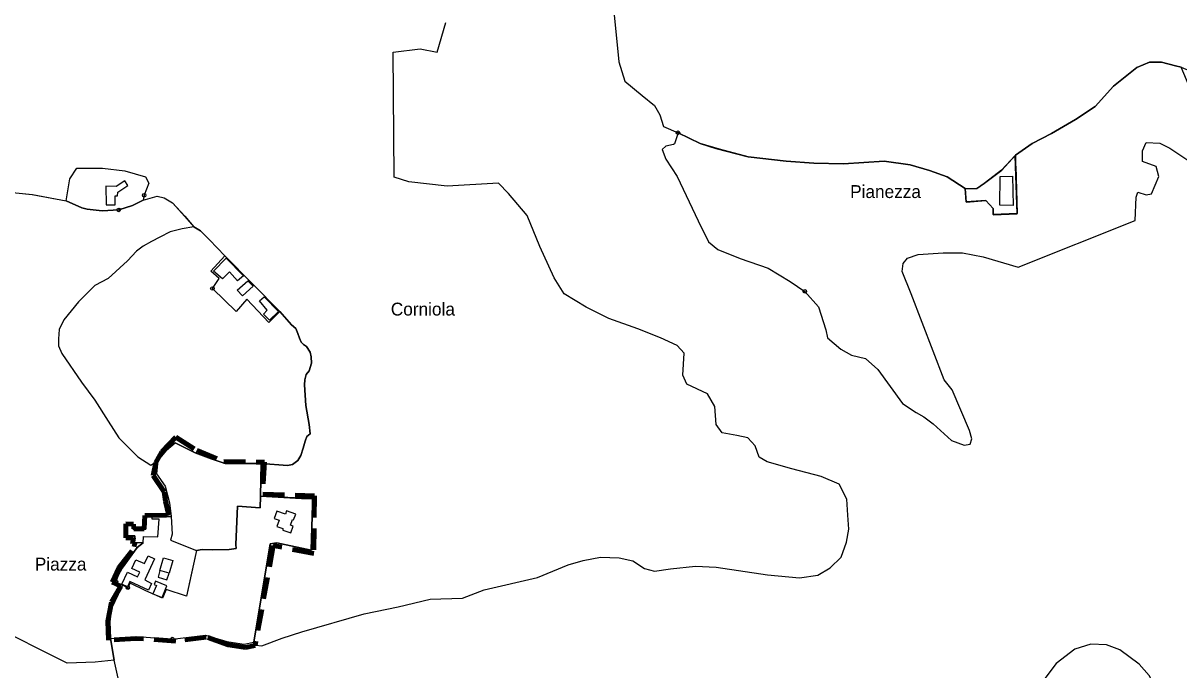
# Model space of a CAD drawing. Extents: x 652791 to 656927, y 889884 to 892405.
# Drawn here: x 655576 to 656474, y 890630 to 891133 of the extents above; entities that cross this region are included whole.
import ezdxf
from ezdxf.enums import TextEntityAlignment as Align

# ---------------------------------------------------------------- set-up
doc = ezdxf.new("R2010")
doc.units = 0
doc.header["$LTSCALE"] = 5.6
doc.header["$PDMODE"] = 32
doc.header["$PDSIZE"] = 2.8
doc.linetypes.add('MEDIUM_DASHED', pattern=[4.5, 3, -1.5])
for name, color, linetype, lineweight in [('1', 7, 'Continuous', 25), ('12', 7, 'Continuous', 25), ('2', 7, 'Continuous', 25), ('3', 7, 'Continuous', 25), ('35', 7, 'Continuous', 25), ('36', 7, 'Continuous', 25), ('37', 7, 'Continuous', 25), ('4', 7, 'Continuous', 25), ('6', 7, 'Continuous', 25), ('7', 7, 'MEDIUM_DASHED', 100)]:
    doc.layers.add(name, color=color, linetype=linetype, lineweight=lineweight)
doc.layers.add('60', color=7, linetype='Continuous')

msp = doc.modelspace()

# ---------------------------------------------------------------- linework, layer by layer
at = {"layer": '1'}
msp.add_line((655647.79, 890698.77), (655649.57, 890703.78), dxfattribs=at)
for points in [[(655649.57, 890703.78), (655652.57, 890709.54), (655664.32, 890725.65), (655668.89, 890729.13), (655662.28, 890729.46), (655662.45, 890734.52), (655656.71, 890734.52), (655656.76, 890743.16), (655660.15, 890743.1), (655661.16, 890739.83), (655670.97, 890739.81), (655671.21, 890749.71), (655690.79, 890749.71), (655691.6, 890735.82), (655690.08, 890731.27), (655710.46, 890723.26)], [(655710.46, 890723.26), (655702.73, 890687.68), (655702.73, 890687.68), (655686.92, 890692.88), (655683.99, 890686.3)], [(655683.99, 890686.3), (655671.13, 890691.84), (655658.88, 890697.92), (655657.03, 890694.32)]]:
    msp.add_lwpolyline(points, dxfattribs=at)
for points in [[(655656.76, 890743.16), (655656.71, 890734.52), (655662.45, 890734.52), (655662.28, 890729.46), (655665.58, 890729.3), (655668.89, 890729.13), (655669.21, 890734), (655680.33, 890733.88), (655681.28, 890747.57), (655675.84, 890747.65), (655675.92, 890749.55), (655671.21, 890749.71), (655670.97, 890739.81), (655661.16, 890739.83), (655660.15, 890743.1)], [(655663.36, 890716.08), (655669.96, 890713), (655672.8, 890719.08), (655677.85, 890716.72), (655670.25, 890700.46), (655675.47, 890697.47), (655673.05, 890692.3), (655658.63, 890699.05), (655656.71, 890694.98), (655652.27, 890697.08), (655656.67, 890706.41), (655664.53, 890702.7), (655666.26, 890706.37), (655660.14, 890709.26)], [(655684.82, 890717.43), (655691.99, 890715.33), (655689.19, 890705.47), (655682.02, 890707.57)], [(655682.02, 890707.57), (655680.64, 890702.48), (655687.34, 890700.47), (655689.19, 890705.47)], [(655678.56, 890699.41), (655677.5, 890696.82), (655679.23, 890696.11), (655676.52, 890689.53), (655683.62, 890686.61), (655687.38, 890695.77)]]:
    msp.add_lwpolyline(points, close=True, dxfattribs=at)
for p in [(655647.79, 890698.77), (655657.03, 890694.32)]:
    msp.add_point(p, dxfattribs=at)
at = {"layer": '12'}
for points in [[(655760.74, 890790.66), (655732.63, 890790.72), (655721.67, 890794.44), (655709.28, 890799.08), (655707.66, 890799.98), (655706.87, 890800.29), (655693.81, 890806.84), (655687.08, 890801.22), (655680.47, 890792.99), (655679.34, 890782.76), (655686.08, 890773.27), (655689.34, 890760.2), (655690.79, 890749.71), (655691.6, 890735.82)], [(655710.46, 890723.26), (655714.74, 890724.03), (655722.92, 890723.72), (655735.74, 890723.97), (655741.29, 890724.86), (655740.98, 890727.97), (655742.36, 890757.53), (655759.74, 890756.34), (655760.24, 890765.34), (655760.74, 890790.66)], [(655754.95, 890652.05), (655767.67, 890728.28), (655772.86, 890729.16), (655799.61, 890723.34), (655800.55, 890758.9), (655800.55, 890763.53), (655791.98, 890763.72), (655760.24, 890765.34), (655759.74, 890756.34), (655742.36, 890757.53)], [(655742.36, 890757.53), (655740.98, 890727.97), (655741.29, 890724.86)], [(655691.6, 890735.82), (655690.08, 890731.27), (655710.46, 890723.26)], [(655710.46, 890723.26), (655706.6, 890705.47), (655702.73, 890687.68), (655686.92, 890692.88), (655683.99, 890686.3), (655671.13, 890691.84), (655658.88, 890697.92), (655657.03, 890694.31), (655653.01, 890696.25), (655649.42, 890689.08), (655644.24, 890678.15), (655643.15, 890667.92), (655643.55, 890654.98), (655663.88, 890656.42), (655671.37, 890655.88), (655691.59, 890654.42)], [(655741.29, 890724.86), (655735.74, 890723.97), (655722.92, 890723.72), (655714.74, 890724.03), (655710.46, 890723.26)], [(655691.59, 890654.42), (655717.46, 890657.36), (655733.95, 890652.58), (655747.37, 890650.41), (655754.95, 890652.05)]]:
    msp.add_lwpolyline(points, dxfattribs=at)
at = {"layer": '2'}
for points in [[(655609.01, 890994.88), (655611.84, 891011.93), (655617.48, 891020.1), (655637.34, 891020.1), (655654.68, 891018.08), (655670.8, 891013.54), (655673.43, 891008.6), (655669.7, 890999.12), (655668.99, 890995.18), (655660.62, 890991.15), (655649.94, 890987.72)], [(655649.94, 890987.72), (655637.19, 890986.97), (655625.49, 890988.27), (655621.19, 890989.37), (655609.01, 890994.88)]]:
    msp.add_lwpolyline(points, dxfattribs=at)
msp.add_lwpolyline([(655639.96, 891006.08), (655640.06, 890991.55), (655647.12, 890991.55), (655647.12, 890998.61), (655649.11, 890998.71), (655649.24, 891001.64), (655657.1, 891006.68), (655654.78, 891010.31), (655647.92, 891005.97)], close=True, dxfattribs=at)
msp.add_point((655649.94, 890987.72), dxfattribs=at)
at = {"layer": '3'}
for points in [[(655721.56, 890940.03), (655732.42, 890952.03), (655775.12, 890908.95), (655766.69, 890900.17), (655749.39, 890918.47), (655741.09, 890908.87), (655722.79, 890926.67)], [(655722.79, 890926.67), (655728.05, 890934.38), (655721.56, 890940.03)]]:
    msp.add_lwpolyline(points, dxfattribs=at)
for points in [[(655730.48, 890934.33), (655723.67, 890940.16), (655733.34, 890950.13), (655746.86, 890936.65), (655742.33, 890932.56), (655735.97, 890939.6)], [(655742.05, 890925.4), (655750.34, 890932.64), (655754.3, 890928.4), (655746.01, 890921.06)], [(655759.32, 890917.09), (655762.9, 890920.32), (655774.01, 890908.76), (655767.09, 890902.2), (655762.33, 890906.83), (655765.29, 890909.98)]]:
    msp.add_lwpolyline(points, close=True, dxfattribs=at)
msp.add_point((655722.79, 890926.67), dxfattribs=at)
at = {"layer": '35'}
msp.add_line((655647.79, 890698.77), (655653.01, 890696.26), dxfattribs=at)
for points in [[(655557.14, 891002.34), (655582.82, 890999.62), (655609.01, 890994.88), (655621.19, 890989.37), (655625.49, 890988.27), (655637.19, 890986.97), (655649.94, 890987.72), (655660.62, 890991.15), (655668.99, 890995.18), (655679.88, 890998.36), (655685.32, 890997.23), (655691.81, 890993.28), (655701.38, 890982.75)], [(655701.38, 890982.75), (655708.23, 890974.6), (655699.33, 890972.91)], [(655699.33, 890972.91), (655690, 890970.58), (655682, 890966.58), (655675.34, 890963.24), (655669.01, 890959.58), (655663.68, 890955.58), (655656.69, 890948.25), (655641.7, 890934.58), (655631.37, 890928.91), (655618.71, 890916.25), (655607.39, 890902.25), (655603.72, 890894.92), (655603.06, 890887.59), (655603.06, 890882.25), (655605.72, 890876.25), (655621.04, 890853.92), (655631.37, 890839.92), (655641.7, 890823.59), (655650.02, 890810.59), (655664.68, 890795.93), (655675.01, 890789.59), (655680.47, 890792.99), (655679.34, 890782.76), (655686.08, 890773.27), (655689.34, 890760.2), (655690.79, 890749.71)], [(655690.79, 890749.71), (655671.21, 890749.71), (655670.97, 890739.81), (655661.16, 890739.83), (655660.15, 890743.1), (655656.76, 890743.16), (655656.71, 890734.52), (655662.45, 890734.52), (655662.28, 890729.46), (655668.89, 890729.13), (655664.32, 890725.65), (655652.57, 890709.54), (655649.57, 890703.78), (655647.79, 890698.77)], [(655653.01, 890696.25), (655649.42, 890689.08), (655644.24, 890678.15), (655643.15, 890667.92), (655643.55, 890654.98), (655646.5, 890637.96), (655641.53, 890637.43)], [(655641.53, 890637.43), (655631.75, 890636.44), (655609.85, 890635.63), (655548.75, 890666.18)]]:
    msp.add_lwpolyline(points, dxfattribs=at)
msp.add_lwpolyline([(655693.81, 890806.84), (655709.28, 890799.08), (655721.67, 890794.44), (655732.63, 890790.72), (655760.74, 890790.66), (655781.06, 890789.26), (655785.07, 890790.12), (655789.08, 890792.99), (655791.38, 890797.01), (655793.39, 890802.75), (655794.82, 890808.2), (655796.25, 890811.64), (655798.83, 890813.93), (655797.97, 890821.11), (655795.39, 890835.74), (655794.82, 890843.77), (655794.25, 890851.81), (655794.53, 890855.82), (655795.68, 890859.84), (655797.97, 890862.71), (655799.69, 890868.73), (655799.41, 890873.61), (655798.83, 890877.34), (655795.97, 890881.64), (655793.67, 890883.08), (655791.66, 890885.09), (655790.52, 890888.24), (655789.08, 890891.68), (655787.65, 890895.7), (655784.21, 890898.57), (655775.12, 890908.95), (655766.69, 890900.17), (655749.39, 890918.47), (655741.09, 890908.87), (655722.79, 890926.67), (655728.05, 890934.38), (655721.56, 890940.03), (655732.42, 890952.03), (655720.55, 890964.56), (655713.39, 890971.44), (655708.23, 890974.6), (655699.33, 890972.91), (655690, 890970.58), (655682, 890966.58), (655675.34, 890963.24), (655669.01, 890959.58), (655663.68, 890955.58), (655656.69, 890948.25), (655641.7, 890934.58), (655631.37, 890928.91), (655618.71, 890916.25), (655607.39, 890902.25), (655603.72, 890894.92), (655603.06, 890887.59), (655603.06, 890882.25), (655605.72, 890876.25), (655621.04, 890853.92), (655631.37, 890839.92), (655641.7, 890823.59), (655650.02, 890810.59), (655664.68, 890795.93), (655675.01, 890789.59), (655680.47, 890792.99), (655687.08, 890801.22)], close=True, dxfattribs=at)
at = {"layer": '36'}
for points in [[(656034.63, 891141.71), (656038.53, 891102.67), (656043.15, 891087.83), (656056.63, 891076.54), (656066.21, 891068.79)], [(656107.51, 890844.89), (656091.53, 890852.4), (656088.44, 890859.4), (656089.47, 890876.4), (656083.8, 890882.4), (656070.91, 890888.4), (656053.38, 890895.4), (656030.7, 890903.41), (656013.18, 890912.12), (655996, 890922.49), (655988.42, 890934.91), (655984.3, 890943.92), (655977.08, 890959.42), (655967.29, 890983.42), (655952.85, 891000.43), (655945.15, 891008.51), (655905.11, 891006.15), (655875.32, 891009.61), (655863.98, 891013.11), (655863.11, 891110.32), (655884.21, 891112.73), (655897.47, 891110.32), (655904.1, 891133.25)], [(656066.21, 891068.79), (656070.39, 891061.56), (656073.22, 891052.53), (656084.58, 891047.69), (656081.74, 891038.98), (656081.03, 891038.65), (656075, 891037.36), (656072.16, 891034.78), (656075, 891027.04), (656083.87, 891013.81), (656100.19, 890979.29), (656108.35, 890962.84), (656115.44, 890957.03), (656132.76, 890949.96), (656154.75, 890942.54), (656171.78, 890932.22), (656183.14, 890924.48), (656193.78, 890912.54), (656199.46, 890894.48), (656200.88, 890888.35), (656211.17, 890879.63), (656219.33, 890874.8), (656230.32, 890872.21), (656239.9, 890863.83), (656259.06, 890837.37), (656269.71, 890830.27), (656275.74, 890827.05), (656282.83, 890821.56), (656297.03, 890808.66), (656306.96, 890805.11), (656311.57, 890805.76), (656312.99, 890809.95), (656311.22, 890816.4), (656297.73, 890848.02), (656291.35, 890855.76), (656265.83, 890922.44), (656258.73, 890939.86), (656259.44, 890945.99), (656262.99, 890950.18), (656271.15, 890953.09)], [(656271.15, 890953.09), (656290.75, 890954.4), (656305.7, 890954.4), (656321.68, 890951.4), (656348.97, 890943.33), (656439.8, 890979.46), (656440.51, 890997.53), (656441.93, 891001.4), (656448.32, 890999.46), (656452.57, 891000.11), (656458.25, 891013.66), (656456.12, 891021.4), (656445.48, 891025.27), (656445.48, 891033.66), (656448.32, 891040.11), (656458.96, 891039.47), (656466.77, 891035.6), (656481.67, 891025.92)], [(655761.27, 890649.28), (655776.89, 890655.05), (655792.34, 890660.05), (655840.64, 890674.02), (655867.17, 890679.45), (655892.03, 890685.35), (655917.21, 890686.09), (655934.03, 890692.7), (655975.29, 890702.29), (655999.14, 890712.01), (656010.98, 890715.31), (656024.41, 890717.97), (656038.96, 890717.41), (656049.45, 890715.17), (656058.55, 890709.29), (656066.25, 890707.05), (656078.7, 890709.01), (656098.15, 890710.97), (656114.24, 890710.13), (656154.01, 890704.34), (656178.9, 890702.01), (656193.15, 890704.08), (656202.75, 890709.79), (656211.3, 890718.09), (656215.45, 890729.77), (656217.27, 890739.88), (656216.49, 890750.52), (656215.76, 890763.07), (656209.75, 890774.65), (656195.75, 890780.62), (656172.97, 890786.57), (656153.9, 890792.07), (656147.71, 890795.57), (656144.62, 890804.57), (656138.95, 890810.58), (656130.18, 890812.58), (656118.84, 890814.58), (656114.2, 890821.08), (656113.17, 890835.08), (656107.51, 890844.89)], [(655697.99, 890568.01), (655688.91, 890571.17), (655676.81, 890576.59), (655668.2, 890582.46), (655661.45, 890589.46), (655656.56, 890598.49), (655653.31, 890606.61), (655650.07, 890621.67), (655646.5, 890637.96), (655643.55, 890654.98), (655663.88, 890656.42), (655671.37, 890655.88), (655691.59, 890654.42)], [(655691.59, 890654.42), (655717.46, 890657.36), (655733.95, 890652.58), (655747.37, 890650.41), (655754.95, 890652.05), (655756.3, 890649.77), (655761.27, 890649.28)], [(656481.61, 890596.03), (656464.08, 890608.04), (656456.35, 890615.04), (656450.68, 890626.04), (656442.94, 890635.04), (656427.99, 890646.04), (656417.68, 890650.04), (656405.31, 890650.54), (656392.94, 890646.54), (656378.5, 890635.54), (656364.13, 890616.47), (656344.54, 890582.96), (656334.72, 890566.93), (656325.76, 890573.55), (656304.66, 890584.23), (656286.87, 890588.74), (656275.35, 890589.99), (656265.33, 890588.49), (656257.31, 890583.22), (656249.3, 890572.95), (656242.24, 890567.05), (656228.32, 890589.55)]]:
    msp.add_lwpolyline(points, dxfattribs=at)
msp.add_point((655691.59, 890654.42), dxfattribs=at)
at = {"layer": '37'}
msp.add_line((655669.7, 890999.12), (655668.99, 890995.18), dxfattribs=at)
for points in [[(656034.63, 891141.71), (656038.53, 891102.67), (656043.15, 891087.83), (656056.63, 891076.54), (656066.21, 891068.79)], [(656346.76, 891030.15), (656359.82, 891039.27), (656374.91, 891047.18), (656393.59, 891057.96), (656408.69, 891068.03), (656423.06, 891083.85), (656441.02, 891098.23), (656451.08, 891102.54), (656460.42, 891102.54), (656471.2, 891099.67), (656475.55, 891098.58), (656489.19, 891092.99), (656505.69, 891087.49), (656521.15, 891086.99), (656530.43, 891088.49), (656539.2, 891093.99), (656550.54, 891114), (656575.8, 891148.01)], [(656107.51, 890844.89), (656091.53, 890852.4), (656088.44, 890859.4), (656089.47, 890876.4), (656083.8, 890882.4), (656070.91, 890888.4), (656053.38, 890895.4), (656030.7, 890903.41), (656013.18, 890912.12), (655996, 890922.49), (655988.42, 890934.91), (655984.3, 890943.92), (655977.08, 890959.42), (655967.29, 890983.42), (655952.85, 891000.43), (655945.15, 891008.51), (655905.11, 891006.15), (655875.32, 891009.61), (655863.98, 891013.11), (655863.11, 891110.32), (655884.21, 891112.73), (655897.47, 891110.32), (655904.1, 891133.25)], [(656471.2, 891099.67), (656460.42, 891102.54), (656451.08, 891102.54), (656441.02, 891098.23), (656423.06, 891083.85), (656408.69, 891068.03), (656393.59, 891057.96), (656374.91, 891047.18), (656359.82, 891039.27), (656346.76, 891030.15), (656346.97, 891021.75), (656347.02, 891021.8), (656348.15, 890984.82), (656329.53, 890984.13), (656329.53, 890988.93), (656323.82, 890995.11), (656308.49, 890993.97), (656307.81, 891004.27)], [(656466.77, 891035.6), (656481.67, 891025.92), (656490.18, 891031.73), (656501.54, 891030.43), (656512.18, 891022.69), (656516.44, 891027.21), (656512.18, 891033.02), (656508.63, 891042.69), (656505.79, 891051.73), (656508.63, 891060.12), (656509.34, 891067.21), (656502.95, 891073.02), (656488.76, 891077.54), (656483.09, 891080.76), (656475.55, 891098.58), (656471.2, 891099.67)], [(656066.21, 891068.79), (656070.39, 891061.56), (656073.22, 891052.53), (656084.58, 891047.69)], [(656116.93, 891034.95), (656101.84, 891039.27), (656084.58, 891047.69), (656081.74, 891038.98), (656081.03, 891038.65), (656075, 891037.36), (656072.16, 891034.78), (656075, 891027.04), (656083.87, 891013.81), (656100.19, 890979.29), (656108.35, 890962.84), (656115.44, 890957.03), (656132.76, 890949.96), (656154.75, 890942.54), (656171.78, 890932.22), (656183.14, 890924.48)], [(656084.58, 891047.69), (656101.84, 891039.27), (656113.9, 891035.54), (656139.05, 891029.07)], [(656190.08, 891024.04), (656168.67, 891025.61), (656139.05, 891029.07), (656116.93, 891034.95)], [(656183.14, 890924.48), (656193.78, 890912.54), (656199.46, 890894.48), (656200.88, 890888.35), (656211.17, 890879.63), (656219.33, 890874.8), (656230.32, 890872.21), (656239.9, 890863.83), (656259.06, 890837.37), (656269.71, 890830.27), (656275.74, 890827.05), (656282.83, 890821.56), (656297.03, 890808.66), (656306.96, 890805.11), (656311.57, 890805.76), (656312.99, 890809.95), (656311.22, 890816.4), (656297.73, 890848.02), (656291.35, 890855.76), (656265.83, 890922.44), (656258.73, 890939.86), (656259.44, 890945.99), (656262.99, 890950.18), (656271.15, 890953.09), (656290.75, 890954.4), (656305.7, 890954.4), (656321.68, 890951.4), (656348.97, 890943.33), (656439.8, 890979.46), (656440.51, 890997.53), (656441.93, 891001.4), (656448.32, 890999.46), (656452.57, 891000.11), (656458.25, 891013.66), (656456.12, 891021.4), (656445.48, 891025.27), (656445.48, 891033.66), (656448.32, 891040.11), (656458.96, 891039.47), (656466.77, 891035.6)], [(656139.05, 891029.07), (656168.67, 891025.61), (656190.08, 891024.04), (656213.23, 891023.45), (656244.69, 891025.48), (656264.97, 891022.73), (656280.06, 891018.42), (656293.71, 891013.38), (656307.81, 891004.27), (656316.73, 891004.27), (656322.67, 891008.39), (656336.16, 891018.69), (656346.76, 891030.15)], [(656307.81, 891004.27), (656293.71, 891013.38), (656280.06, 891018.42), (656264.97, 891022.73), (656244.69, 891025.48), (656213.23, 891023.45), (656190.08, 891024.04)], [(655488.11, 891022.12), (655502.57, 891014.96), (655516.74, 891009.33), (655529.83, 891005.76), (655543.36, 891002.72), (655557.14, 891002.33), (655582.81, 890999.61), (655609.01, 890994.87), (655611.84, 891011.93), (655617.48, 891020.1), (655637.34, 891020.1), (655654.68, 891018.08), (655670.8, 891013.54), (655673.43, 891008.6), (655669.7, 890999.12)], [(655668.99, 890995.18), (655679.87, 890998.35), (655685.31, 890997.22), (655691.81, 890993.28), (655701.38, 890982.74), (655708.22, 890974.59)], [(655708.22, 890974.59), (655713.38, 890971.44), (655720.55, 890964.55), (655732.42, 890952.03), (655775.12, 890908.95)], [(655775.12, 890908.95), (655784.21, 890898.57), (655787.65, 890895.7), (655789.08, 890891.68), (655790.51, 890888.24), (655791.66, 890885.08), (655793.67, 890883.07), (655795.96, 890881.64), (655798.83, 890877.33), (655799.4, 890873.61), (655799.69, 890868.73), (655797.97, 890862.7), (655795.68, 890859.83), (655794.53, 890855.82), (655794.24, 890851.8), (655794.82, 890843.77), (655795.39, 890835.73), (655797.97, 890821.1), (655798.83, 890813.93), (655796.25, 890811.64), (655794.82, 890808.19), (655793.38, 890802.74), (655791.38, 890797), (655789.08, 890792.99), (655785.07, 890790.12), (655781.05, 890789.26), (655760.74, 890790.65), (655760.24, 890765.33), (655791.98, 890763.71)], [(655761.27, 890649.28), (655776.89, 890655.05), (655792.34, 890660.05), (655840.64, 890674.02), (655867.17, 890679.45), (655892.03, 890685.35), (655917.21, 890686.09), (655934.03, 890692.7), (655975.29, 890702.29), (655999.14, 890712.01), (656010.98, 890715.31), (656024.41, 890717.97), (656038.96, 890717.41), (656049.45, 890715.17), (656058.55, 890709.29), (656066.25, 890707.05), (656078.7, 890709.01), (656098.15, 890710.97), (656114.24, 890710.13), (656154.01, 890704.34), (656178.9, 890702.01), (656193.15, 890704.08), (656202.75, 890709.79), (656211.3, 890718.09), (656215.45, 890729.77), (656217.27, 890739.88), (656216.49, 890750.52), (656215.76, 890763.07), (656209.75, 890774.65), (656195.75, 890780.62), (656172.97, 890786.57), (656153.9, 890792.07), (656147.71, 890795.57), (656144.62, 890804.57), (656138.95, 890810.58), (656130.18, 890812.58), (656118.84, 890814.58), (656114.2, 890821.08), (656113.17, 890835.08), (656107.51, 890844.89)], [(655791.98, 890763.71), (655800.55, 890763.52), (655800.55, 890758.89), (655799.61, 890723.33), (655772.86, 890729.15), (655767.67, 890728.27), (655754.95, 890652.05), (655756.3, 890649.77), (655761.27, 890649.28)], [(655646.5, 890637.96), (655631.75, 890636.44), (655609.85, 890635.63), (655548.75, 890666.18), (655543.59, 890653.67), (655537.99, 890649.56), (655523.59, 890650.1), (655513.34, 890653.12), (655505.81, 890658.55), (655502.49, 890665.79), (655499.48, 890673.64), (655497.39, 890676.63), (655486, 890689.35), (655478.76, 890700.82), (655486, 890709.87), (655491.42, 890720.13), (655489.01, 890728.58), (655481.78, 890732.2), (655474.54, 890724.96), (655466.7, 890727.97), (655451.06, 890726.93), (655441.49, 890728.27), (655456.86, 890701.91)], [(656481.61, 890596.03), (656464.08, 890608.04), (656456.35, 890615.04), (656450.68, 890626.04), (656442.94, 890635.04), (656427.99, 890646.04), (656417.68, 890650.04), (656405.31, 890650.54), (656392.94, 890646.54), (656378.5, 890635.54), (656364.13, 890616.47), (656344.54, 890582.96), (656334.72, 890566.93)], [(655650.07, 890621.67), (655646.5, 890637.96)]]:
    msp.add_lwpolyline(points, dxfattribs=at)
for p in [(656084.58, 891047.69), (655669.7, 890999.12), (656183.14, 890924.48)]:
    msp.add_point(p, dxfattribs=at)
at = {"layer": '4'}
for points in [[(656346.91, 891021.65), (656346.7, 891030.05), (656336.1, 891018.59), (656322.61, 891008.29), (656316.67, 891004.17), (656307.75, 891004.17), (656308.43, 890993.87), (656323.76, 890995.01), (656329.47, 890988.83), (656329.47, 890984.03)], [(656329.47, 890984.03), (656348.09, 890984.72), (656346.96, 891021.7)]]:
    msp.add_lwpolyline(points, dxfattribs=at)
msp.add_lwpolyline([(656335.02, 891013.64), (656344.44, 891013.88), (656344.92, 890991.18), (656334.78, 890991.42)], close=True, dxfattribs=at)
at = {"layer": '6'}
msp.add_lwpolyline([(655787.46, 890751.41), (655780.3, 890753.95), (655779.43, 890751.5), (655772.83, 890753.85), (655770.76, 890748.01), (655774.52, 890746.67), (655772.85, 890741.96), (655777.37, 890740.35), (655777.54, 890739.02), (655783.57, 890736.87), (655785.44, 890742.15), (655783.37, 890742.89), (655784.91, 890747.22), (655785.85, 890746.89)], close=True, dxfattribs=at)
at = {"layer": '7'}
for points in [[(655651.54, 890695.38), (655644.95, 890698.68), (655649.95, 890709.67), (655663.93, 890727.59), (655660.72, 890728.36), (655661.55, 890733.16), (655655.39, 890733.04), (655655.51, 890743.84), (655661.31, 890743.65), (655661.72, 890740.12), (655669.6, 890740.12), (655670.32, 890750.3), (655688.81, 890750.73), (655686.17, 890761.43), (655685.31, 890768.68), (655676.66, 890781.33), (655678.82, 890791.44), (655683.51, 890799.79), (655694.33, 890811.11), (655710.55, 890801.05), (655731.58, 890792.37), (655763.15, 890791.72), (655761.86, 890766.91), (655802.12, 890765.61), (655801.47, 890720.82)], [(655801.47, 890720.82), (655769.99, 890727.08), (655756.03, 890649.47)], [(655756.03, 890649.47), (655748.45, 890647.83), (655735.03, 890650), (655717.9, 890655.95), (655694.37, 890652.88), (655663.29, 890654.94), (655641.94, 890653.51), (655641.36, 890668.28), (655644.23, 890683.19), (655651.54, 890695.38)]]:
    msp.add_lwpolyline(points, dxfattribs=at)

# ---------------------------------------------------------------- texts
at = {"layer": '60'}
for s, p in [('Pianezza', (656245.86, 890996.96)), ('Corniola', (655886.31, 890905.69)), ('Piazza', (655604.83, 890707.63))]:
    msp.add_text(s, height=10, dxfattribs=at).set_placement(p, align=Align.CENTER)

doc.saveas('drawing.dxf')
